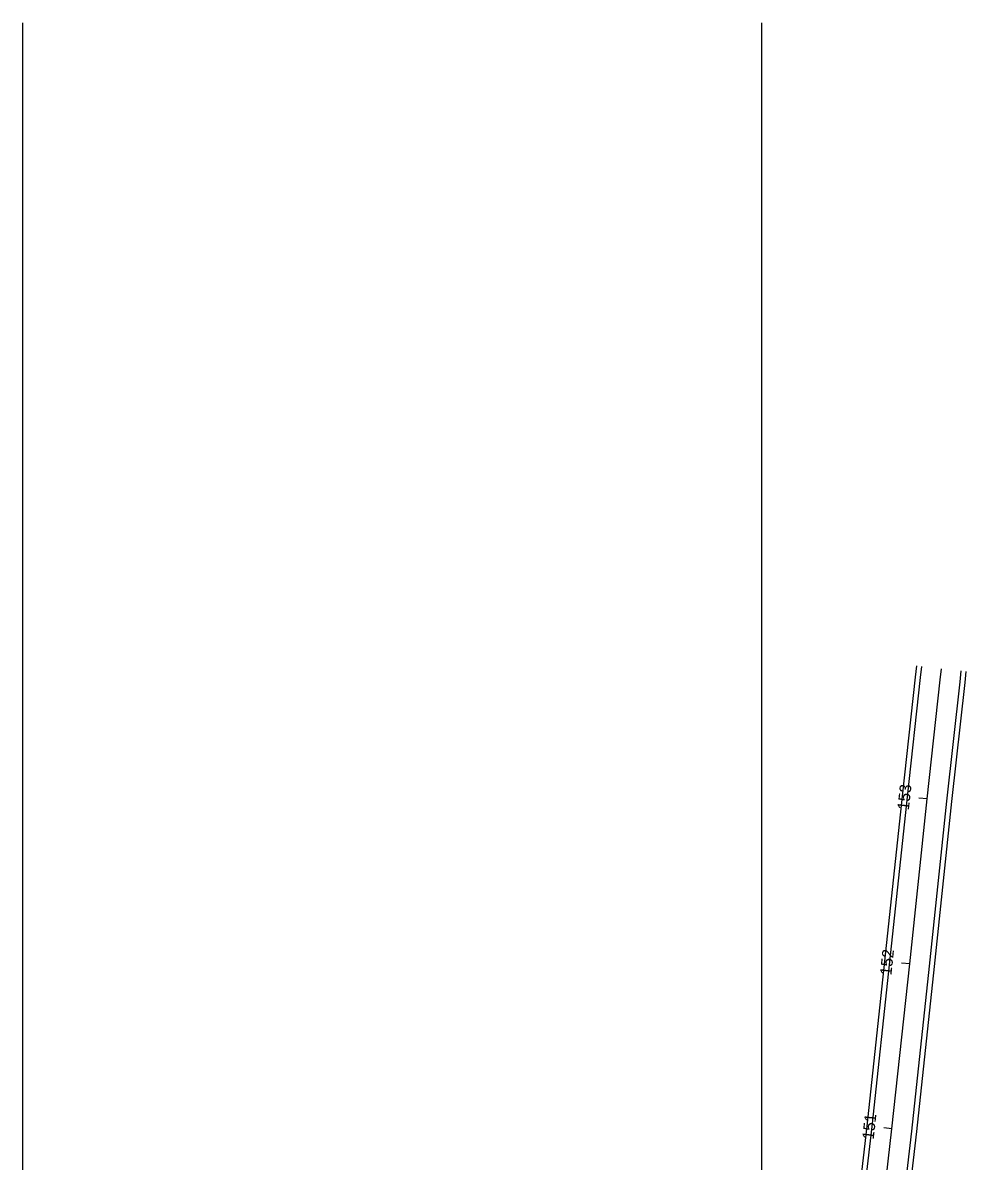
# Model space of a CAD drawing. Extents: x 2318076 to 2324211, y 613525 to 630327.
# Drawn here: x 2320224 to 2320793, y 629641 to 630327 of the extents above; entities that cross this region are included whole.
import ezdxf

# ---------------------------------------------------------------- set-up
doc = ezdxf.new("R2010")
doc.units = 0
for name, color, linetype in [('GE_P_CL_50', 7, 'Continuous'), ('PV_X_Shoulder', 7, 'Continuous'), ('RS_Raster1', 7, 'Continuous'), ('SC_Scratch3', 7, 'Continuous')]:
    doc.layers.add(name, color=color, linetype=linetype)

msp = doc.modelspace()

# ---------------------------------------------------------------- linework, layer by layer
at = {"layer": 'GE_P_CL_50'}
for p, q in [((2320769.62, 629859.3), (2320764.65, 629859.85)), ((2320759.09, 629759.86), (2320754.11, 629760.38)), ((2320748.4, 629660.43), (2320743.43, 629660.98))]:
    msp.add_line(p, q, dxfattribs=at)
msp.add_lwpolyline([(2320476.3, 627307.7), (2320485.22, 627375.57), (2320502.11, 627520.92), (2320519.22, 627676.47), (2320531.82, 627783.89), (2320546.8, 627927.12), (2320554.45, 627991.34), (2320572.51, 628138.41), (2320649.52, 628804.84), (2320678.77, 629064.5), (2320690.76, 629163.78), (2320713.75, 629362.45), (2320725.26, 629461.78), (2320736.97, 629561.09), (2320748.4, 629660.43), (2320759.09, 629759.86), (2320769.62, 629859.3), (2320777.51, 629931.12), (2320778.25, 629937.84)], dxfattribs=at)
at = {"layer": 'PV_X_Shoulder'}
for points in [[(2320705.21, 629419), (2320733.49, 629662.09), (2320744.17, 629761.45), (2320754.71, 629860.91), (2320762.6, 629932.76), (2320763.34, 629939.48)], [(2320735.01, 629415.55), (2320763.31, 629658.77), (2320774, 629758.27), (2320784.54, 629857.69), (2320792.42, 629929.48), (2320793.16, 629936.2)]]:
    msp.add_lwpolyline(points, dxfattribs=at)
at = {"layer": 'RS_Raster1'}
for points in [[(2320708.13, 629418.9), (2320736.47, 629661.76), (2320747.15, 629761.13), (2320757.69, 629860.59), (2320765.58, 629932.43), (2320766.32, 629939.15)], [(2320731.95, 629415.91), (2320760.33, 629659.11), (2320771.02, 629758.59), (2320781.55, 629858.02), (2320789.44, 629929.81), (2320790.18, 629936.53)]]:
    msp.add_lwpolyline(points, dxfattribs=at)
at = {"layer": 'SC_Scratch3'}
for p, q in [((2320224.38, 614778.41), (2320224.38, 630327.22)), ((2320669.87, 614778.41), (2320669.87, 630327.22))]:
    msp.add_line(p, q, dxfattribs=at)

# ---------------------------------------------------------------- texts
at = {"layer": 'GE_P_CL_50'}
for s, rotation, p in [('153', 83.73288, (2320758.54, 629852.29)), ('152', 84.07858, (2320748.04, 629752.76)), ('151', 83.76642, (2320737.35, 629653.72))]:
    msp.add_text(s, height=7, rotation=rotation, dxfattribs=at).set_placement(p)

doc.saveas('drawing.dxf')
